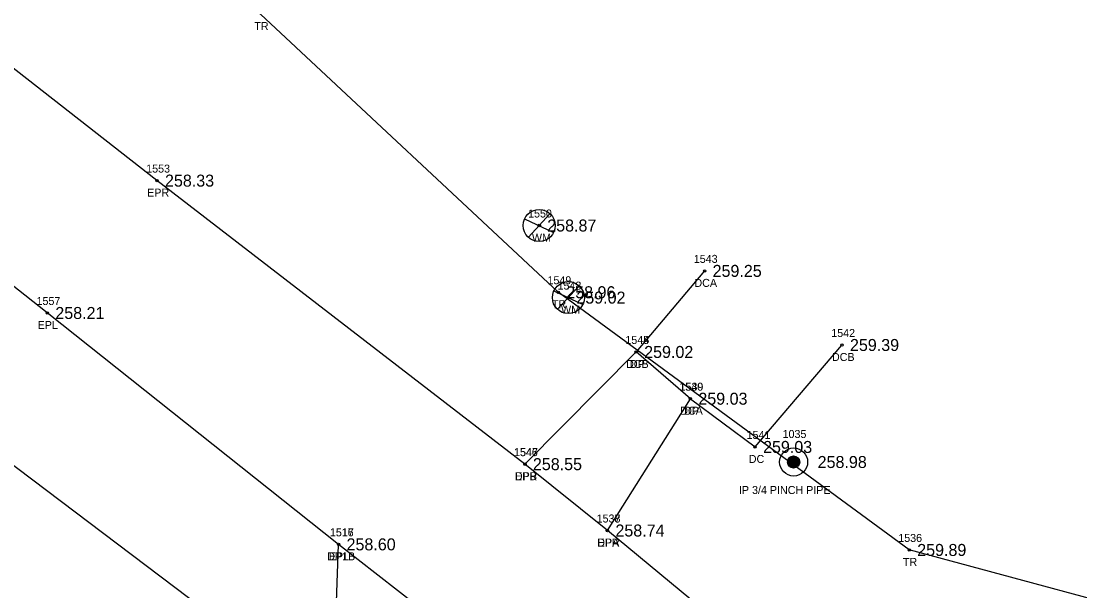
# Model space of a CAD drawing. Extents: x 1961231 to 1962574, y 799865 to 801120.
# Drawn here: x 1961578.2 to 1961710.5, y 800823.2 to 800894.4 of the extents above; entities that cross this region are included whole.
import ezdxf

# ---------------------------------------------------------------- set-up
doc = ezdxf.new("R2010")
doc.units = 0
for name, color, linetype in [('RD_EX_Conc', 7, 'Continuous'), ('RD_EX_Conc_txCode', 7, 'Continuous'), ('RD_EX_Driveway', 7, 'Continuous'), ('RD_EX_Driveway_txCode', 7, 'Continuous'), ('RD_EX_DV_Prop_txCode', 7, 'Continuous'), ('RD_EX_DV_PropPin', 7, 'Continuous'), ('RD_EX_Road', 7, 'Continuous'), ('RD_EX_Road_txCode', 7, 'Continuous'), ('RD_EX_TX_Conc_ELEV', 7, 'Continuous'), ('RD_EX_TX_Driveway_ELEV', 7, 'Continuous'), ('RD_EX_TX_DV_Prop_ELEV', 7, 'Continuous'), ('RD_EX_TX_Road_ELEV', 7, 'Continuous'), ('RD_EX_TX_UT_ELEV', 7, 'Continuous'), ('RD_EX_TX_VEG_ELEV', 7, 'Continuous'), ('RD_EX_UT', 7, 'Continuous'), ('RD_EX_UT_txCode', 7, 'Continuous'), ('RD_EX_VEG', 7, 'Continuous'), ('RD_EX_VEG_txCode', 7, 'Continuous'), ('RD_SMD_Locator', 7, 'Continuous')]:
    doc.layers.add(name, color=color, linetype=linetype)

msp = doc.modelspace()

# ---------------------------------------------------------------- linework, layer by layer
at = {"layer": 'RD_EX_Conc'}
msp.add_line((1961663.59, 800863.17), (1961655.04, 800853.04), dxfattribs=at)
msp.add_lwpolyline([(1961661.81, 800847.2), (1961669.89, 800841.17), (1961680.75, 800853.91)], dxfattribs=at)
at = {"layer": 'RD_EX_Driveway'}
for points in [[(1961651.45, 800830.73), (1961661.81, 800847.2), (1961655.04, 800853.04), (1961641.14, 800839.02)], [(1961637.49, 800813.67), (1961630.98, 800810.92), (1961627.63, 800811.79), (1961617.59, 800799.43), (1961609.66, 800805.67), (1961617.41, 800815.76), (1961617.86, 800829)]]:
    msp.add_lwpolyline(points, dxfattribs=at)
at = {"layer": 'RD_EX_DV_PropPin'}
for p, q in [((1961673.98, 800839.1), (1961673.98, 800839.49)), ((1961674.01, 800839), (1961674.01, 800839.59)), ((1961674.05, 800838.92), (1961674.05, 800839.66)), ((1961674.08, 800838.87), (1961674.08, 800839.72)), ((1961674.12, 800838.82), (1961674.12, 800839.77)), ((1961674.15, 800838.78), (1961674.15, 800839.81)), ((1961674.19, 800838.74), (1961674.19, 800839.84)), ((1961674.22, 800838.71), (1961674.22, 800839.88)), ((1961674.26, 800838.68), (1961674.26, 800839.9)), ((1961674.29, 800838.66), (1961674.29, 800839.93)), ((1961674.33, 800838.64), (1961674.33, 800839.95)), ((1961674.36, 800838.62), (1961674.36, 800839.97)), ((1961674.4, 800838.6), (1961674.4, 800839.99)), ((1961674.43, 800838.59), (1961674.43, 800840)), ((1961674.47, 800838.57), (1961674.47, 800840.01)), ((1961674.5, 800838.56), (1961674.5, 800840.02)), ((1961674.54, 800838.55), (1961674.54, 800840.03)), ((1961674.57, 800838.55), (1961674.57, 800840.04)), ((1961674.61, 800838.54), (1961674.61, 800840.05)), ((1961674.64, 800838.54), (1961674.64, 800840.05)), ((1961674.68, 800838.53), (1961674.68, 800840.05)), ((1961674.71, 800838.53), (1961674.71, 800840.05)), ((1961674.75, 800838.53), (1961674.75, 800840.05)), ((1961674.78, 800838.54), (1961674.78, 800840.05)), ((1961674.82, 800838.54), (1961674.82, 800840.05)), ((1961674.85, 800838.55), (1961674.85, 800840.04)), ((1961674.89, 800838.55), (1961674.89, 800840.03)), ((1961674.92, 800838.56), (1961674.92, 800840.02)), ((1961674.96, 800838.57), (1961674.96, 800840.01)), ((1961674.99, 800838.59), (1961674.99, 800840)), ((1961675.03, 800838.6), (1961675.03, 800839.99)), ((1961675.06, 800838.62), (1961675.06, 800839.97)), ((1961675.1, 800838.64), (1961675.1, 800839.95)), ((1961675.13, 800838.66), (1961675.13, 800839.93)), ((1961675.17, 800838.68), (1961675.17, 800839.9)), ((1961675.2, 800838.71), (1961675.2, 800839.88)), ((1961675.24, 800838.74), (1961675.24, 800839.84)), ((1961675.27, 800838.78), (1961675.27, 800839.81)), ((1961675.31, 800838.82), (1961675.31, 800839.77)), ((1961675.34, 800838.87), (1961675.34, 800839.72)), ((1961675.38, 800838.92), (1961675.38, 800839.66)), ((1961675.41, 800839), (1961675.41, 800839.59)), ((1961675.45, 800839.1), (1961675.45, 800839.49))]:
    msp.add_line(p, q, dxfattribs=at)
for radius in [1.75, 0.761]:
    msp.add_circle((1961674.71, 800839.29), radius, dxfattribs=at)
at = {"layer": 'RD_EX_Road'}
for points in [[(1961735.63, 800762.82), (1961702.92, 800788.52), (1961676.16, 800810.27), (1961651.45, 800830.73), (1961641.14, 800839.02), (1961595.18, 800874.45), (1961552.9, 800907.54), (1961510.92, 800940.49), (1961504.01, 800946.58), (1961476.53, 800968.16), (1961444.88, 800992.72), (1961406.41, 801021.23), (1961370.69, 801045.26)], [(1961722.95, 800745.11), (1961689.13, 800771.93), (1961670.14, 800787.03), (1961660.52, 800795.31), (1961637.49, 800813.67), (1961617.86, 800829), (1961581.48, 800857.91), (1961538.42, 800891.96), (1961505, 800917.96), (1961467.33, 800947.97), (1961432.02, 800975.33), (1961392.71, 801004.33), (1961360.06, 801026.78)]]:
    msp.add_lwpolyline(points, dxfattribs=at)
at = {"layer": 'RD_EX_UT'}
for p, q in [((1961641.1, 800869.68), (1961644.73, 800867.97)), ((1961641.58, 800867.38), (1961644.25, 800870.28)), ((1961645.22, 800858.38), (1961647.88, 800861.27)), ((1961644.74, 800860.67), (1961648.37, 800858.96))]:
    msp.add_line(p, q, dxfattribs=at)
for centre in [(1961642.93, 800868.84), (1961646.57, 800859.83)]:
    msp.add_circle(centre, 2, dxfattribs=at)
at = {"layer": 'RD_EX_VEG'}
for points in [[(1961789.73, 800785.49), (1961758.16, 800795.77), (1961726.49, 800818.25), (1961689.15, 800828.3), (1961645.31, 800860.5), (1961608.13, 800895.26), (1961564.66, 800923.57), (1961511.61, 800961.39)], [(1961584.58, 800795.58), (1961602.69, 800819.62), (1961568.89, 800845.14), (1961527.21, 800877.9), (1961471.95, 800913.34)]]:
    msp.add_lwpolyline(points, dxfattribs=at)
at = {"layer": 'RD_SMD_Locator'}
for centre in [(1961595.18, 800874.45), (1961642.93, 800868.84), (1961663.59, 800863.17), (1961645.31, 800860.5), (1961646.57, 800859.83), (1961581.48, 800857.91), (1961680.75, 800853.91), (1961655.04, 800853.04), (1961655.04, 800853.04), (1961661.81, 800847.2), (1961661.81, 800847.2), (1961669.89, 800841.17), (1961641.14, 800839.02), (1961641.14, 800839.02), (1961674.71, 800839.29), (1961651.45, 800830.73), (1961651.45, 800830.73), (1961617.86, 800829), (1961617.86, 800829), (1961689.15, 800828.3)]:
    msp.add_circle(centre, 0.15, dxfattribs=at)

# ---------------------------------------------------------------- texts
at = {"layer": 'RD_EX_Conc_txCode'}
for s, p in [('1543', (1961662.24, 800864.17)), ('DCA', (1961662.32, 800861.17)), ('1544', (1961653.69, 800854.04)), ('1542', (1961679.41, 800854.91)), ('DCB', (1961653.78, 800851.04)), ('DCB', (1961679.5, 800851.91)), ('1540', (1961660.42, 800848.2)), ('DCA', (1961660.54, 800845.2)), ('1541', (1961668.83, 800842.17)), ('DC', (1961669.11, 800839.17))]:
    msp.add_text(s, height=1, dxfattribs=at).set_placement(p)
at = {"layer": 'RD_EX_Driveway_txCode'}
for s, p in [('1545', (1961653.69, 800854.04)), ('DP', (1961654.26, 800851.04)), ('1539', (1961660.46, 800848.2)), ('DP', (1961661.03, 800845.2)), ('1547', (1961639.8, 800840.02)), ('DPB', (1961639.89, 800837.02)), ('1538', (1961650.1, 800831.73)), ('1516', (1961616.77, 800830)), ('DPA', (1961650.18, 800828.73)), ('DP1B', (1961616.44, 800827))]:
    msp.add_text(s, height=1, dxfattribs=at).set_placement(p)
at = {"layer": 'RD_EX_DV_Prop_txCode'}
for s, p in [('1035', (1961673.33, 800842.29)), ('IP 3/4 PINCH PIPE', (1961667.88, 800835.29))]:
    msp.add_text(s, height=1, dxfattribs=at).set_placement(p)
at = {"layer": 'RD_EX_Road_txCode'}
for s, p in [('1553', (1961593.83, 800875.45)), ('EPR', (1961593.95, 800872.45)), ('1557', (1961580.13, 800858.91)), ('EPL', (1961580.27, 800855.91)), ('1546', (1961639.77, 800840.02)), ('EPR', (1961639.91, 800837.02)), ('1537', (1961650.1, 800831.73)), ('1517', (1961616.79, 800830)), ('EPR', (1961650.22, 800828.73)), ('EPL', (1961616.65, 800827))]:
    msp.add_text(s, height=1, dxfattribs=at).set_placement(p)
at = {"layer": 'RD_EX_TX_Conc_ELEV'}
for s, p in [('259.25', (1961664.59, 800862.42)), ('259.39', (1961681.75, 800853.16)), ('259.02', (1961656.04, 800852.29)), ('259.03', (1961662.81, 800846.45)), ('259.03', (1961670.89, 800840.42))]:
    msp.add_text(s, height=1.5, dxfattribs=at).set_placement(p)
at = {"layer": 'RD_EX_TX_Driveway_ELEV'}
for s, p in [('259.02', (1961656.04, 800852.29)), ('259.03', (1961662.81, 800846.45)), ('258.55', (1961642.14, 800838.27)), ('258.74', (1961652.45, 800829.98)), ('258.60', (1961618.86, 800828.25))]:
    msp.add_text(s, height=1.5, dxfattribs=at).set_placement(p)
at = {"layer": 'RD_EX_TX_DV_Prop_ELEV'}
msp.add_text('258.98', height=1.5, dxfattribs=at).set_placement((1961677.71, 800838.54))
at = {"layer": 'RD_EX_TX_Road_ELEV'}
for s, p in [('258.33', (1961596.18, 800873.7)), ('258.21', (1961582.48, 800857.16)), ('258.55', (1961642.14, 800838.27)), ('258.74', (1961652.45, 800829.98)), ('258.60', (1961618.86, 800828.25))]:
    msp.add_text(s, height=1.5, dxfattribs=at).set_placement(p)
at = {"layer": 'RD_EX_TX_UT_ELEV'}
for s, p in [('258.87', (1961643.93, 800868.09)), ('259.02', (1961647.57, 800859.08))]:
    msp.add_text(s, height=1.5, dxfattribs=at).set_placement(p)
at = {"layer": 'RD_EX_TX_VEG_ELEV'}
for s, p in [('258.96', (1961646.31, 800859.75)), ('259.89', (1961690.15, 800827.55))]:
    msp.add_text(s, height=1.5, dxfattribs=at).set_placement(p)
at = {"layer": 'RD_EX_UT_txCode'}
for s, p in [('1550', (1961641.54, 800869.84)), ('WM', (1961642.02, 800866.84)), ('1548', (1961645.22, 800860.83)), ('WM', (1961645.66, 800857.83))]:
    msp.add_text(s, height=1, dxfattribs=at).set_placement(p)
at = {"layer": 'RD_EX_VEG_txCode'}
for s, p in [('TR', (1961607.34, 800893.26)), ('1549', (1961643.96, 800861.5)), ('TR', (1961644.51, 800858.5)), ('1536', (1961687.78, 800829.3)), ('TR', (1961688.36, 800826.3))]:
    msp.add_text(s, height=1, dxfattribs=at).set_placement(p)

doc.saveas('drawing.dxf')
